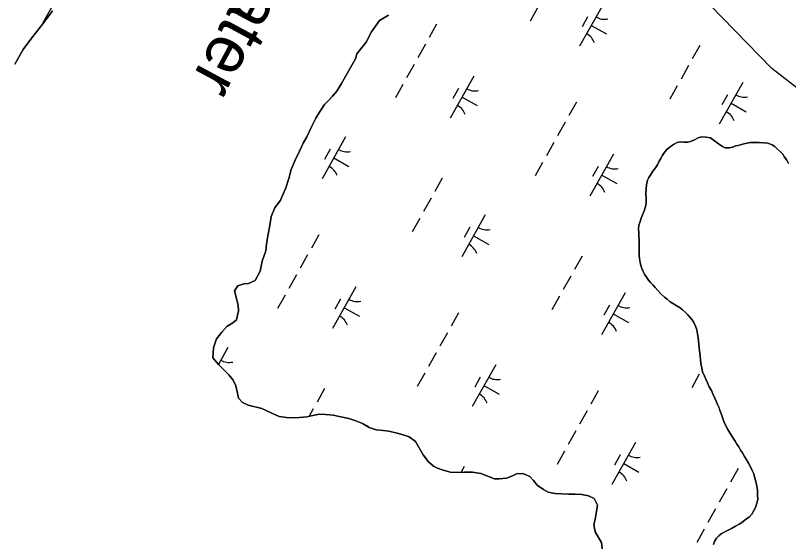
# Model space of a CAD drawing. Extents: x 3923531 to 3943530, y 207391 to 229799.
# Drawn here: x 3936825 to 3937629, y 217296 to 217845 of the extents above; entities that cross this region are included whole.
import ezdxf

# ---------------------------------------------------------------- set-up
doc = ezdxf.new("R2010")
doc.units = 0
for name, color, linetype in [('V-RIVR-IDEN', 7, 'Continuous'), ('V-SITE-VEGE', 7, 'Continuous'), ('V-TOPO-SHOR', 7, 'Continuous'), ('V-WETL-SWMP', 7, 'Continuous')]:
    doc.layers.add(name, color=color, linetype=linetype)

msp = doc.modelspace()

# ---------------------------------------------------------------- linework, layer by layer
at = {"layer": 'V-SITE-VEGE'}
msp.add_lwpolyline([(3937552.25, 217970.4), (3937619.2, 217906), (3937647.52, 217872.5), (3937696.44, 217818.4), (3937735.06, 217777.18), (3937753.09, 217733.39), (3937737.64, 217712.77), (3937691.29, 217728.23), (3937611.47, 217790.06), (3937534.23, 217869.93), (3937467.28, 217898.27), (3937379.73, 217903.42), (3937323.09, 217924.03), (3937312.79, 217972.98), (3937338.54, 218011.62), (3937382.31, 218032.24), (3937431.23, 218039.96), (3937467.28, 218032.24), (3937487.88, 218019.35), (3937523.93, 217991.01)], close=True, dxfattribs=at)
at = {"layer": 'V-TOPO-SHOR'}
for points in [[(3936863.62, 217850.02), (3936853.71, 217836.37), (3936842.39, 217821.94), (3936833.3, 217809.87), (3936824.77, 217794.61)], [(3937212.98, 217845.66), (3937203.75, 217839.98), (3937195.26, 217828.3), (3937189.76, 217817.4), (3937180.17, 217805.24), (3937178.82, 217800.17), (3937174.46, 217792.64), (3937169.99, 217784.91), (3937164.3, 217774.4), (3937159.23, 217766.48), (3937154.79, 217761.14), (3937150.76, 217756.6), (3937146.53, 217752.46), (3937141.27, 217744.74), (3937137.41, 217738.4), (3937132.93, 217729.27), (3937128.04, 217718.76), (3937124.39, 217712.42), (3937120.51, 217703.89), (3937116.03, 217694.76), (3937111.94, 217684.83), (3937109.25, 217675.69), (3937106.36, 217665.76), (3937100.85, 217653.05)], [(3937477.54, 217578.9), (3937476.38, 217582.11), (3937475.25, 217585.03), (3937474.72, 217588.18), (3937473.97, 217592.34), (3937473.68, 217595.45), (3937473.61, 217599.76), (3937473.53, 217603.98), (3937473.65, 217607.49), (3937473.53, 217611.48), (3937473.22, 217616.03), (3937473.33, 217619.21), (3937472.85, 217622.77), (3937473.09, 217626.95), (3937474.12, 217629.93), (3937475.56, 217634.3), (3937476.99, 217637.68), (3937478.83, 217642.05), (3937480.27, 217646.42), (3937480.71, 217649.8), (3937480.76, 217654.79), (3937480.61, 217659.77), (3937480.66, 217664.75), (3937481.3, 217669.13), (3937482.35, 217673.71), (3937483.57, 217676.49), (3937485.6, 217679.85), (3937487.63, 217683.22), (3937490.45, 217686.58), (3937492.48, 217689.95), (3937494.32, 217693.72), (3937495.94, 217696.29), (3937497.56, 217699.07), (3937499.59, 217702.44), (3937502.42, 217705.79), (3937506.04, 217708.95), (3937509.25, 217711.11), (3937513.06, 217713.06), (3937516.05, 217713.63), (3937520.04, 217713.39), (3937524.03, 217713.55), (3937527.02, 217713.91), (3937531.03, 217715.86), (3937534.84, 217717.82), (3937538.44, 217718.98), (3937543.22, 217718.73), (3937547.6, 217717.89), (3937551.95, 217714.85), (3937556.1, 217711.82), (3937560.26, 217708.78), (3937563.04, 217707.56), (3937566.83, 217707.52), (3937570.82, 217708.28), (3937573.62, 217709.44), (3937576.62, 217709.81), (3937581.02, 217711.36), (3937584.22, 217711.93), (3937588.81, 217712.87), (3937593.8, 217713.02), (3937598.18, 217712.98), (3937602.96, 217712.73), (3937607.15, 217712.29), (3937611.71, 217710.44), (3937614.48, 217708.82), (3937617.25, 217706.2), (3937620.61, 217703.38), (3937622.77, 217700.76), (3937624.74, 217697.75), (3937626.9, 217694.54), (3937628.86, 217691.33)], [(3937100.85, 217653.05), (3937094.98, 217645.14), (3937091.1, 217636.21), (3937089.81, 217626.65), (3937087.92, 217617.7), (3937086.22, 217607.75), (3937085.35, 217600.39), (3937081.85, 217589.46), (3937079.55, 217579.31), (3937074.46, 217569.6), (3937067.65, 217566.28), (3937062.66, 217565.93), (3937056.26, 217563.81), (3937053.02, 217558.66), (3937056.85, 217543.86), (3937057.19, 217537.88), (3937054.9, 217528.53), (3937051.08, 217525.58), (3937044.86, 217521.46), (3937039.62, 217515.73), (3937034.36, 217508.61), (3937031.27, 217499.27), (3937030.57, 217488.92)], [(3937550.67, 217294.94), (3937552.31, 217298.51), (3937553.93, 217301.29), (3937556.35, 217303.85), (3937558.76, 217305.82), (3937561.77, 217307.58), (3937564.78, 217309.15), (3937569.38, 217311.49), (3937573.6, 217313.84), (3937577.4, 217315.8), (3937581.42, 217318.55), (3937584.03, 217320.71), (3937587.85, 217323.27), (3937590.67, 217326.43), (3937592.9, 217330.19), (3937594.33, 217333.17), (3937596.18, 217338.93), (3937596.81, 217342.11), (3937596.46, 217346.3), (3937596.51, 217351.48), (3937595.96, 217355.48), (3937595.2, 217359.07), (3937593.89, 217363.95), (3937592.66, 217368.35), (3937591.1, 217371.87), (3937589.04, 217376.44), (3937587.27, 217379.37), (3937584.64, 217383.5), (3937583.08, 217386.39), (3937580.81, 217390.16), (3937579.04, 217392.85), (3937577, 217396.38), (3937575.08, 217399.07), (3937573.27, 217402.4), (3937570.61, 217406.53), (3937567.94, 217411.15), (3937565.79, 217414.6), (3937563.12, 217418.97), (3937561.49, 217422.9), (3937560.09, 217427.02), (3937559.05, 217430.18), (3937557.85, 217433.66), (3937556.54, 217437.42), (3937554.97, 217440.47), (3937553.61, 217443.87), (3937552.05, 217447.08), (3937550.14, 217451.56), (3937548.58, 217454.93), (3937546.31, 217458.94), (3937544.44, 217462.9), (3937542.76, 217466.67), (3937541.32, 217470.03), (3937539.5, 217474.6), (3937538.77, 217478.11), (3937537.75, 217483.03), (3937537.15, 217487.02), (3937536.92, 217491.17), (3937536.29, 217496.16), (3937535.96, 217499.47), (3937535.6, 217503.03), (3937535.16, 217506.54), (3937534.8, 217509.89), (3937534.16, 217514.04), (3937533.41, 217518.24), (3937532.25, 217521.96), (3937530.26, 217525.81), (3937528.49, 217528.42), (3937526.52, 217531.03), (3937524.12, 217533.84), (3937521.87, 217536.26), (3937518.75, 217539.08), (3937516.14, 217541.06), (3937511.94, 217543.54), (3937509.25, 217545.32), (3937505.72, 217547.31), (3937502.68, 217549.97), (3937499.95, 217552), (3937496, 217555.51), (3937492.88, 217558.97), (3937490.12, 217562.27), (3937487.72, 217564.92), (3937485.16, 217567.5), (3937483.23, 217569.91), (3937481.02, 217572.96), (3937478.98, 217575.98), (3937477.54, 217578.9)], [(3937030.57, 217488.92), (3937036.48, 217481.88), (3937042, 217476.44), (3937046.93, 217471.2), (3937051.46, 217465.77), (3937054.19, 217459.76), (3937055.91, 217452.17), (3937057.25, 217447.17), (3937061.39, 217442.54), (3937067.14, 217439.89), (3937081.46, 217436.16), (3937085.82, 217434.12), (3937092.57, 217431.06), (3937099.31, 217428), (3937107.08, 217426.92), (3937113.85, 217426.65), (3937120.44, 217426.98), (3937128.22, 217427.7), (3937134.21, 217429.03), (3937141.4, 217430.35), (3937147.58, 217430.09), (3937155.34, 217429.21), (3937163.5, 217427.73), (3937171.86, 217425.85), (3937179.21, 217423.58), (3937185.96, 217420.72), (3937192.89, 217416.66), (3937200.24, 217413.99), (3937207.41, 217413.32), (3937213.19, 217412.66), (3937222.14, 217410.58), (3937228.3, 217408.92), (3937234.45, 217406.66), (3937241.18, 217401.81), (3937249.01, 217387.97), (3937254.52, 217380.74), (3937259.66, 217376.3), (3937264.02, 217374.26), (3937268.79, 217372.62), (3937276.94, 217369.94), (3937285.91, 217369.85), (3937291.49, 217369.99), (3937300.46, 217369.9), (3937308.82, 217368.61), (3937315.18, 217366.36), (3937323.32, 217363.28), (3937327.9, 217363.04), (3937335.69, 217363.95), (3937341.29, 217365.89), (3937345.9, 217368.43), (3937352.48, 217368.56), (3937360.02, 217365.69), (3937363.57, 217361.27), (3937367.7, 217356.44), (3937374.04, 217351.99), (3937378.99, 217349.35), (3937385.76, 217347.88), (3937392.93, 217347.61), (3937400.3, 217347.33), (3937406.88, 217347.07), (3937413.85, 217346.79), (3937421.02, 217345.52), (3937426.77, 217342.67), (3937430.29, 217335.86), (3937427.74, 217320.93), (3937426.29, 217315.56), (3937427.81, 217307.97), (3937434.27, 217296.94), (3937435.2, 217290.15)]]:
    msp.add_lwpolyline(points, dxfattribs=at)
at = {"layer": 'V-WETL-SWMP'}
for p, q in [((3936877.98, 217881.03), (3936853.59, 217837.38)), ((3937436.01, 217856.74), (3937411.63, 217813.09)), ((3936853.71, 217836.37), (3936863.62, 217850.02)), ((3937367.92, 217853.2), (3937360.12, 217839.24)), ((3937420.01, 217843.92), (3937414.16, 217833.44)), ((3936842.39, 217821.94), (3936853.71, 217836.37)), ((3937263.06, 217836.19), (3937255.25, 217822.22)), ((3937423.82, 217834.92), (3937439.53, 217826.14)), ((3936833.3, 217809.87), (3936842.39, 217821.94)), ((3937251.35, 217815.24), (3937243.55, 217801.27)), ((3937536.55, 217813.98), (3937528.74, 217800.02)), ((3936824.77, 217794.61), (3936833.3, 217809.87)), ((3937239.65, 217794.28), (3937231.84, 217780.32)), ((3937524.84, 217793.03), (3937517.04, 217779.06)), ((3937301.61, 217782.1), (3937277.22, 217738.44)), ((3937227.94, 217773.33), (3937220.14, 217759.36)), ((3937581.22, 217775.62), (3937556.84, 217731.97)), ((3937285.6, 217769.27), (3937279.75, 217758.79)), ((3937513.14, 217772.08), (3937505.33, 217758.11)), ((3937289.41, 217760.27), (3937305.13, 217751.49)), ((3937565.22, 217762.79), (3937559.37, 217752.32)), ((3937408.27, 217755.06), (3937400.47, 217741.1)), ((3937569.03, 217753.79), (3937584.75, 217745.01)), ((3937396.56, 217734.11), (3937388.76, 217720.14)), ((3937168.4, 217718.78), (3937144.02, 217675.13)), ((3937384.86, 217713.16), (3937377.06, 217699.19)), ((3937152.4, 217705.96), (3937146.55, 217695.48)), ((3937446.82, 217700.97), (3937422.43, 217657.32)), ((3937156.21, 217696.96), (3937171.93, 217688.18)), ((3937373.15, 217692.21), (3937365.35, 217678.24)), ((3937430.82, 217688.15), (3937424.96, 217677.67)), ((3937434.63, 217679.15), (3937450.34, 217670.37)), ((3937268.94, 217676.02), (3937261.14, 217662.06)), ((3937257.23, 217655.07), (3937249.43, 217641.1)), ((3937313.62, 217637.66), (3937289.23, 217594.01)), ((3937245.53, 217634.12), (3937237.73, 217620.15)), ((3937297.62, 217624.83), (3937291.76, 217614.36)), ((3937140.66, 217617.1), (3937132.86, 217603.14)), ((3937301.43, 217615.83), (3937317.14, 217607.05)), ((3937128.96, 217596.15), (3937121.15, 217582.18)), ((3937414.15, 217594.9), (3937406.35, 217580.93)), ((3937117.25, 217575.2), (3937109.45, 217561.23)), ((3937402.45, 217573.95), (3937394.65, 217559.98)), ((3937179.21, 217563.01), (3937154.83, 217519.36)), ((3937458.83, 217556.53), (3937434.45, 217512.88)), ((3937105.55, 217554.25), (3937097.74, 217540.28)), ((3937163.21, 217550.19), (3937157.36, 217539.71)), ((3937390.74, 217553), (3937382.94, 217539.03)), ((3937167.02, 217541.19), (3937182.73, 217532.41)), ((3937442.83, 217543.71), (3937436.98, 217533.23)), ((3937285.88, 217535.98), (3937278.07, 217522.01)), ((3937446.64, 217534.71), (3937462.35, 217525.93)), ((3937274.17, 217515.03), (3937266.37, 217501.06)), ((3937046.01, 217499.7), (3937036.22, 217482.18)), ((3937262.47, 217494.07), (3937254.66, 217480.11)), ((3937324.43, 217481.89), (3937300.04, 217438.24)), ((3937047.95, 217469.98), (3937049.53, 217469.09)), ((3937250.76, 217473.12), (3937242.96, 217459.15)), ((3937308.42, 217469.06), (3937302.57, 217458.59)), ((3937535.96, 217471.87), (3937528.15, 217457.9)), ((3937312.23, 217460.06), (3937327.95, 217451.28)), ((3937146.55, 217456.94), (3937138.74, 217442.97)), ((3937431.09, 217454.85), (3937423.29, 217440.89)), ((3937134.84, 217435.99), (3937130.5, 217428.21)), ((3937419.39, 217433.9), (3937411.58, 217419.93)), ((3937191.23, 217418.57), (3937190.83, 217417.87)), ((3937407.68, 217412.95), (3937399.88, 217398.98)), ((3937469.64, 217400.76), (3937445.25, 217357.11)), ((3937395.98, 217392), (3937388.17, 217378.03)), ((3937453.64, 217387.94), (3937447.79, 217377.46)), ((3937291.76, 217375.82), (3937288.46, 217369.91)), ((3937457.45, 217378.94), (3937473.16, 217370.16)), ((3937576.3, 217373.73), (3937568.5, 217359.76)), ((3937564.6, 217352.78), (3937556.8, 217338.81)), ((3937552.89, 217331.83), (3937545.09, 217317.86)), ((3937541.19, 217310.87), (3937533.39, 217296.91))]:
    msp.add_line(p, q, dxfattribs=at)
for points in [[(3937030.57, 217488.92), (3937031.27, 217499.27), (3937034.36, 217508.61), (3937039.62, 217515.73), (3937044.86, 217521.46), (3937051.08, 217525.58), (3937054.9, 217528.53), (3937057.19, 217537.88), (3937056.85, 217543.86), (3937053.02, 217558.66), (3937056.26, 217563.81), (3937062.66, 217565.93), (3937067.65, 217566.28), (3937074.46, 217569.6), (3937079.55, 217579.31), (3937081.85, 217589.46), (3937085.35, 217600.39), (3937086.22, 217607.75), (3937087.92, 217617.7), (3937089.81, 217626.65), (3937091.1, 217636.21), (3937094.98, 217645.14), (3937100.85, 217653.05), (3937106.36, 217665.76), (3937109.25, 217675.69), (3937111.94, 217684.84), (3937116.03, 217694.76), (3937120.51, 217703.89), (3937124.39, 217712.42), (3937128.04, 217718.76), (3937132.93, 217729.27), (3937137.41, 217738.4), (3937141.27, 217744.74), (3937146.53, 217752.46), (3937150.76, 217756.6), (3937154.79, 217761.14), (3937159.23, 217766.48), (3937164.3, 217774.4), (3937169.99, 217784.91), (3937174.46, 217792.64), (3937178.82, 217800.17), (3937180.17, 217805.24), (3937189.76, 217817.4), (3937195.26, 217828.3), (3937203.75, 217839.98), (3937212.98, 217845.66)], [(3937628.86, 217691.33), (3937626.9, 217694.54), (3937624.74, 217697.75), (3937622.77, 217700.76), (3937620.61, 217703.38), (3937617.25, 217706.2), (3937614.49, 217708.82), (3937611.71, 217710.44), (3937607.15, 217712.29), (3937602.96, 217712.73), (3937598.18, 217712.98), (3937593.8, 217713.02), (3937588.81, 217712.87), (3937584.22, 217711.93), (3937581.02, 217711.36), (3937576.62, 217709.81), (3937573.62, 217709.44), (3937570.82, 217708.28), (3937566.83, 217707.52), (3937563.04, 217707.56), (3937560.26, 217708.78), (3937556.1, 217711.82), (3937551.95, 217714.85), (3937547.6, 217717.89), (3937543.22, 217718.73), (3937538.44, 217718.98), (3937534.84, 217717.82), (3937531.03, 217715.86), (3937527.02, 217713.91), (3937524.03, 217713.55), (3937520.04, 217713.39), (3937516.05, 217713.63), (3937513.06, 217713.06), (3937509.25, 217711.11), (3937506.04, 217708.95), (3937502.42, 217705.8), (3937499.59, 217702.43), (3937497.56, 217699.07), (3937495.94, 217696.29), (3937494.32, 217693.72), (3937492.48, 217689.95), (3937490.46, 217686.58), (3937487.63, 217683.22), (3937485.6, 217679.85), (3937483.57, 217676.49), (3937482.35, 217673.71), (3937481.3, 217669.13), (3937480.66, 217664.75), (3937480.61, 217659.77), (3937480.76, 217654.78), (3937480.71, 217649.8), (3937480.27, 217646.42), (3937478.83, 217642.05), (3937476.99, 217637.68), (3937475.56, 217634.3), (3937474.12, 217629.93), (3937473.09, 217626.95), (3937472.85, 217622.77), (3937473.33, 217619.22), (3937473.22, 217616.03), (3937473.53, 217611.48), (3937473.65, 217607.49), (3937473.53, 217603.98), (3937473.61, 217599.76), (3937473.68, 217595.45), (3937473.97, 217592.34), (3937474.72, 217588.18), (3937475.25, 217585.03), (3937476.38, 217582.11), (3937477.54, 217578.9), (3937478.98, 217575.98), (3937481.03, 217572.97), (3937483.23, 217569.91), (3937485.16, 217567.5), (3937487.72, 217564.92), (3937490.12, 217562.27), (3937492.88, 217558.97), (3937496, 217555.51), (3937499.95, 217552), (3937502.68, 217549.98), (3937505.72, 217547.31), (3937509.25, 217545.32), (3937511.94, 217543.54), (3937516.14, 217541.06), (3937518.75, 217539.08), (3937521.87, 217536.26), (3937524.12, 217533.85), (3937526.52, 217531.03), (3937528.49, 217528.42), (3937530.26, 217525.81), (3937532.25, 217521.96), (3937533.41, 217518.24), (3937534.16, 217514.05)], [(3937534.16, 217514.05), (3937534.8, 217509.89), (3937535.16, 217506.54), (3937535.6, 217503.02), (3937535.96, 217499.47), (3937536.29, 217496.16), (3937536.92, 217491.17), (3937537.15, 217487.02), (3937537.75, 217483.03), (3937538.77, 217478.11), (3937539.5, 217474.6), (3937541.32, 217470.03), (3937542.76, 217466.67), (3937544.44, 217462.9), (3937546.31, 217458.94), (3937548.58, 217454.93), (3937550.14, 217451.56), (3937552.05, 217447.08), (3937553.61, 217443.87), (3937554.97, 217440.47), (3937556.53, 217437.42), (3937557.85, 217433.66), (3937559.05, 217430.18), (3937560.1, 217427.02), (3937561.49, 217422.9), (3937563.12, 217418.97), (3937565.79, 217414.6), (3937567.95, 217411.15), (3937570.61, 217406.53), (3937573.28, 217402.4), (3937575.08, 217399.07), (3937577, 217396.38), (3937579.04, 217392.85), (3937580.81, 217390.16), (3937583.08, 217386.39), (3937584.64, 217383.5), (3937587.27, 217379.37), (3937589.04, 217376.44), (3937591.1, 217371.87), (3937592.66, 217368.35), (3937593.89, 217363.95), (3937595.2, 217359.07), (3937595.96, 217355.48), (3937596.51, 217351.48), (3937596.46, 217346.3), (3937596.81, 217342.11), (3937596.18, 217338.93), (3937594.33, 217333.16), (3937592.9, 217330.19), (3937590.67, 217326.42), (3937587.85, 217323.26), (3937584.03, 217320.71), (3937581.42, 217318.55), (3937577.4, 217315.8), (3937573.6, 217313.84), (3937569.39, 217311.49), (3937564.78, 217309.15), (3937561.77, 217307.58), (3937558.76, 217305.82), (3937556.35, 217303.85), (3937553.93, 217301.29), (3937552.31, 217298.51), (3937550.67, 217294.94)], [(3937378.99, 217349.35), (3937374.04, 217351.99), (3937367.7, 217356.44), (3937363.57, 217361.27), (3937360.02, 217365.69), (3937352.48, 217368.56), (3937345.9, 217368.43), (3937341.29, 217365.89), (3937335.69, 217363.95), (3937327.9, 217363.03), (3937323.32, 217363.28), (3937315.18, 217366.36), (3937308.82, 217368.61), (3937300.46, 217369.9), (3937291.49, 217369.99), (3937285.91, 217369.85), (3937276.94, 217369.94), (3937268.79, 217372.62), (3937264.02, 217374.26), (3937259.66, 217376.3), (3937254.52, 217380.74), (3937249.01, 217387.97), (3937241.18, 217401.81), (3937234.46, 217406.66), (3937228.3, 217408.92), (3937222.14, 217410.58), (3937213.19, 217412.67), (3937207.41, 217413.32), (3937200.24, 217413.99), (3937192.89, 217416.66), (3937185.96, 217420.72), (3937179.21, 217423.58), (3937171.86, 217425.85), (3937163.5, 217427.73), (3937155.35, 217429.21), (3937147.58, 217430.09), (3937141.4, 217430.35), (3937134.21, 217429.03), (3937128.22, 217427.7), (3937120.44, 217426.98), (3937113.85, 217426.65), (3937107.08, 217426.92), (3937099.31, 217428), (3937092.57, 217431.06), (3937085.82, 217434.12), (3937081.46, 217436.16), (3937067.14, 217439.89), (3937061.39, 217442.55), (3937057.25, 217447.17), (3937055.91, 217452.17), (3937054.19, 217459.76), (3937051.46, 217465.77), (3937046.93, 217471.2), (3937042, 217476.44), (3937036.48, 217481.88), (3937030.57, 217488.92)], [(3937435.2, 217290.15), (3937434.27, 217296.94), (3937427.81, 217307.97), (3937426.29, 217315.57), (3937427.74, 217320.93), (3937430.29, 217335.86), (3937426.77, 217342.67), (3937421.02, 217345.52), (3937413.85, 217346.79), (3937406.88, 217347.07), (3937400.3, 217347.33), (3937392.93, 217347.61), (3937385.76, 217347.88), (3937378.99, 217349.35)]]:
    msp.add_lwpolyline(points, dxfattribs=at)
for centre, start, end in [((3937437.5, 217858.91), 240.03808, 281.58174), ((3937410.55, 217810.69), 20.03808, 61.58174), ((3937303.09, 217784.27), 240.03808, 281.58174), ((3937582.71, 217777.79), 240.03808, 281.58174), ((3937276.15, 217736.04), 20.03808, 61.58174), ((3937555.77, 217729.56), 20.03808, 61.58174), ((3937169.89, 217720.95), 240.03808, 281.58174), ((3937142.95, 217672.73), 20.03808, 61.58174), ((3937448.3, 217703.14), 240.03808, 281.58174), ((3937421.36, 217654.92), 20.03808, 61.58174), ((3937315.1, 217639.83), 240.03808, 281.58174), ((3937288.16, 217591.6), 20.03808, 61.58174), ((3937180.7, 217565.18), 240.03808, 281.58174), ((3937460.32, 217558.71), 240.03808, 281.58174), ((3937153.76, 217516.96), 20.03808, 61.58174), ((3937433.38, 217510.48), 20.03808, 61.58174), ((3937047.5, 217501.87), 240.03808, 281.58174), ((3937325.91, 217484.06), 240.03808, 281.58174), ((3937298.97, 217435.83), 20.03808, 61.58174), ((3937471.13, 217402.93), 240.03808, 281.58174), ((3937444.18, 217354.71), 20.03808, 61.58174)]:
    msp.add_arc(centre, 17.62, start, end, dxfattribs=at)

# ---------------------------------------------------------------- texts
at = {"layer": 'V-RIVR-IDEN'}
msp.add_text('Water', height=50, rotation=241.58945, dxfattribs=at).set_placement((3937091.75, 217934.63))

doc.saveas('drawing.dxf')
